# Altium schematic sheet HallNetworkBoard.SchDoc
size A
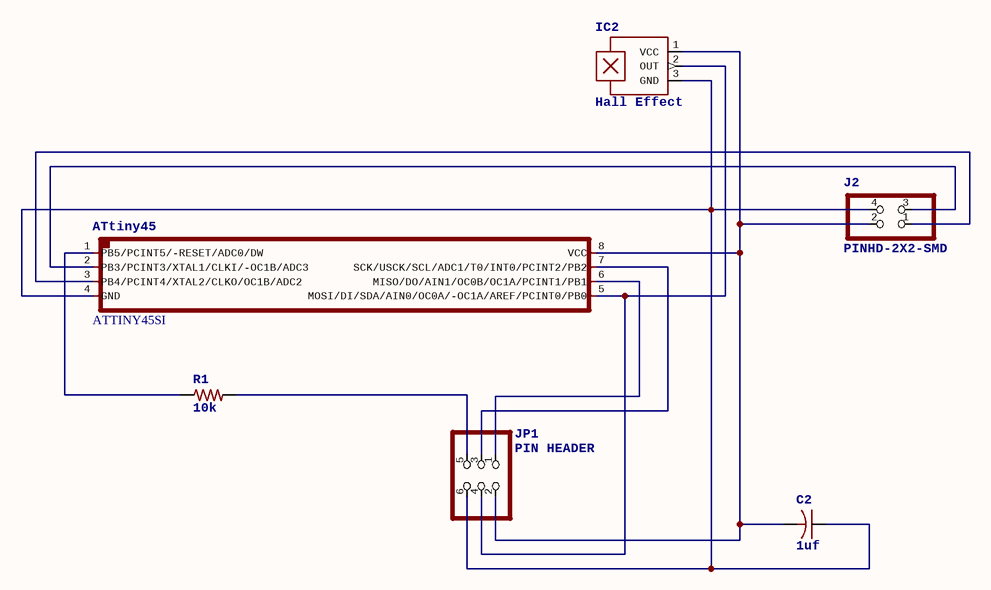
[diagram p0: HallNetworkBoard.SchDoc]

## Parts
ATtiny45  ATTINY45SI  [SOIC8]
C2  1uf  [C1206]
IC2  Hall Effect  [SOT-23]
J2  PINHD-2X2-SMD  [2X02SMD]
JP1  PIN HEADER  [2X03SMD]
R1  10k  [R1206]

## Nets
NetATtiny45_1: ATtiny45.1(PB5/PCINT5/-RESET/ADC0/DW) R1.1
NetATtiny45_2: ATtiny45.2(PB3/PCINT3/XTAL1/CLKI/-OC1B/ADC3) J2.3
NetATtiny45_3: ATtiny45.3(PB4/PCINT4/XTAL2/CLKO/OC1B/ADC2) J2.1
NetATtiny45_4: ATtiny45.4(GND) C2.1 IC2.3(GND) J2.4 JP1.6
NetATtiny45_5: ATtiny45.5(MOSI/DI/SDA/AIN0/OC0A/-OC1A/AREF/PCINT0/PB0) IC2.2(OUT) JP1.4
NetATtiny45_6: ATtiny45.6(MISO/DO/AIN1/OC0B/OC1A/PCINT1/PB1) JP1.1
NetATtiny45_7: ATtiny45.7(SCK/USCK/SCL/ADC1/T0/INT0/PCINT2/PB2) JP1.3
NetATtiny45_8: ATtiny45.8(VCC) C2.2 IC2.1(VCC) J2.2 JP1.2
NetJP1_5: JP1.5 R1.2

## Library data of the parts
C2 = CAP-US1206
IC2 = A13*?LH: pin to pad: 1>3 3>1; MPN: A1301ELHLT-T; MPN: A1302ELHLT-T; MPN: A1321LLHLT-T; MPN: A1322LLHLT-T; MPN: A1323LLHLT-T; MPN: A1381LLHLT-T; MPN: A1382LLHLT-T; MPN: A1383LLHLT-T; MPN: A1384LLHLT-T; MF: ALLEGRO MICROSYSTEMS, INC.
JP1 = PINHD-2X3-SMD
R1 = RES-US1206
